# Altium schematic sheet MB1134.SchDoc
size A4; DocumentNumber: 1; Revision: A.1(PCB.SCH); SheetNumber: 1; SheetTotal: 3; PageSetup: Record=PageOptions|CenterHorizontal=True|CenterVertical=True|PrintScale=1.00|XCorrection=1.00|YCorrection=1.00|PrintKind=1|BorderSize=5000000|LeftOffset=0|BottomOffset=0|Orientation=2|PaperLength=1000|PaperWidth=1000|Scale=100|PaperSource=15|PrintQuality=1200|MediaType=1|DitherType=10|PaperKind=A4|PrintScaleMode=1
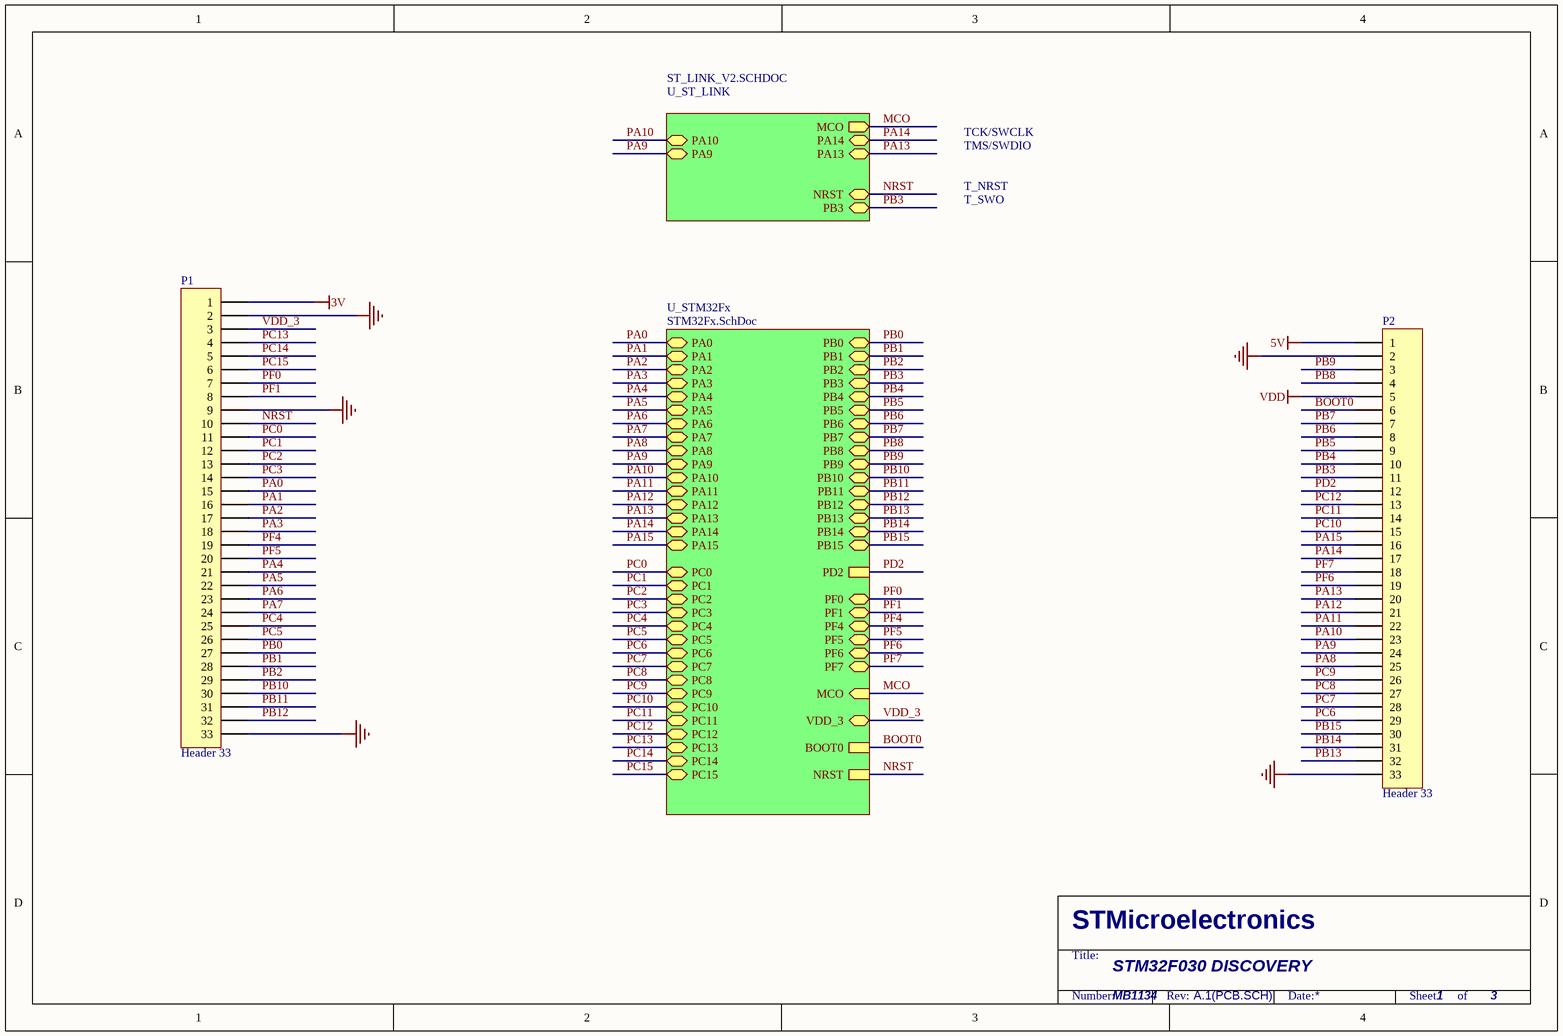
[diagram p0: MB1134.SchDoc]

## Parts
P1  Header 33  [HDR1X33]
P2  Header 33  [HDR1X33]

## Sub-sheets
U_ST_LINK = ST_LINK_V2.SCHDOC: PA13, PA14, NRST, PB3, MCO (out), PA10, PA9
U_STM32Fx = STM32Fx.SchDoc: PA13, PA14, PA15 (bidir), PA12 (bidir), PA0 (bidir), PA1 (bidir), PA2 (bidir), PA3 (bidir), PA4 (bidir), PA5 (bidir), PA6 (bidir), PA7 (bidir), PA8 (bidir), PA9, PA10, PA11 (bidir), PB12 (bidir), PB0 (bidir), PB1 (bidir), PB2 (bidir), PB3, PB4 (bidir), PB5 (bidir), PB6 (bidir), PB7 (bidir), PB8 (bidir), PB9 (bidir), PB10 (bidir), PB11 (bidir), PB13 (bidir), PB14 (bidir), PB15 (bidir), PC3 (bidir), PC15 (bidir), PC14 (bidir), PC13 (bidir), PC12 (bidir), PC11 (bidir), PC10 (bidir), PC9 (bidir), PC8 (bidir), PC7 (bidir), PC6 (bidir), PC5 (bidir), PC4 (bidir), PC2 (bidir), PC1 (bidir), PC0 (bidir), PD2, BOOT0, NRST, MCO (in), VDD_3, PF7, PF6, PF5, PF4, PF1, PF0

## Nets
3V: P1.1
5V: P2.1
GND: P1.2 P1.9 P1.33 P2.2 P2.33
VDD: P2.5
BOOT0: P2.6 ; sheet U_STM32Fx/BOOT0
MCO: sheet U_ST_LINK/MCO, sheet U_STM32Fx/MCO
NRST: P1.10 ; sheet U_ST_LINK/NRST, sheet U_STM32Fx/NRST
PA0: P1.15 ; sheet U_STM32Fx/PA0
PA1: P1.16 ; sheet U_STM32Fx/PA1
PA2: P1.17 ; sheet U_STM32Fx/PA2
PA3: P1.18 ; sheet U_STM32Fx/PA3
PA4: P1.21 ; sheet U_STM32Fx/PA4
PA5: P1.22 ; sheet U_STM32Fx/PA5
PA6: P1.23 ; sheet U_STM32Fx/PA6
PA7: P1.24 ; sheet U_STM32Fx/PA7
PA8: P2.25 ; sheet U_STM32Fx/PA8
PA9: P2.24 ; sheet U_ST_LINK/PA9, sheet U_STM32Fx/PA9
PA10: P2.23 ; sheet U_ST_LINK/PA10, sheet U_STM32Fx/PA10
PA11: P2.22 ; sheet U_STM32Fx/PA11
PA12: P2.21 ; sheet U_STM32Fx/PA12
PA13: P2.20 ; sheet U_ST_LINK/PA13, sheet U_STM32Fx/PA13
PA14: P2.17 ; sheet U_ST_LINK/PA14, sheet U_STM32Fx/PA14
PA15: P2.16 ; sheet U_STM32Fx/PA15
PB0: P1.27 ; sheet U_STM32Fx/PB0
PB1: P1.28 ; sheet U_STM32Fx/PB1
PB2: P1.29 ; sheet U_STM32Fx/PB2
PB3: P2.11 ; sheet U_ST_LINK/PB3, sheet U_STM32Fx/PB3
PB4: P2.10 ; sheet U_STM32Fx/PB4
PB5: P2.9 ; sheet U_STM32Fx/PB5
PB6: P2.8 ; sheet U_STM32Fx/PB6
PB7: P2.7 ; sheet U_STM32Fx/PB7
PB8: P2.4 ; sheet U_STM32Fx/PB8
PB9: P2.3 ; sheet U_STM32Fx/PB9
PB10: P1.30 ; sheet U_STM32Fx/PB10
PB11: P1.31 ; sheet U_STM32Fx/PB11
PB12: P1.32 ; sheet U_STM32Fx/PB12
PB13: P2.32 ; sheet U_STM32Fx/PB13
PB14: P2.31 ; sheet U_STM32Fx/PB14
PB15: P2.30 ; sheet U_STM32Fx/PB15
PC0: P1.11 ; sheet U_STM32Fx/PC0
PC1: P1.12 ; sheet U_STM32Fx/PC1
PC2: P1.13 ; sheet U_STM32Fx/PC2
PC3: P1.14 ; sheet U_STM32Fx/PC3
PC4: P1.25 ; sheet U_STM32Fx/PC4
PC5: P1.26 ; sheet U_STM32Fx/PC5
PC6: P2.29 ; sheet U_STM32Fx/PC6
PC7: P2.28 ; sheet U_STM32Fx/PC7
PC8: P2.27 ; sheet U_STM32Fx/PC8
PC9: P2.26 ; sheet U_STM32Fx/PC9
PC10: P2.15 ; sheet U_STM32Fx/PC10
PC11: P2.14 ; sheet U_STM32Fx/PC11
PC12: P2.13 ; sheet U_STM32Fx/PC12
PC13: P1.4 ; sheet U_STM32Fx/PC13
PC14: P1.5 ; sheet U_STM32Fx/PC14
PC15: P1.6 ; sheet U_STM32Fx/PC15
PD2: P2.12 ; sheet U_STM32Fx/PD2
PF0: P1.7 ; sheet U_STM32Fx/PF0
PF1: P1.8 ; sheet U_STM32Fx/PF1
PF4: P1.19 ; sheet U_STM32Fx/PF4
PF5: P1.20 ; sheet U_STM32Fx/PF5
PF6: P2.19 ; sheet U_STM32Fx/PF6
PF7: P2.18 ; sheet U_STM32Fx/PF7
VDD_3: P1.3 ; sheet U_STM32Fx/VDD_3

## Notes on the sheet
- TCK/SWCLK
- TMS/SWDIO
- T_SWO
- T_NRST
- STM32F030 DISCOVERY
- MB1134
- 1

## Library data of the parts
P1 P2 = Header 33: Header, 33-Pin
